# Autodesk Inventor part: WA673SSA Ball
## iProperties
Category: PARTsolutions
Created: 2011-07
Part Number: WA673SSA Ball
Catalog Web Link: www.cadenas.de
Description: Six types ball - Metric system sizes
Document SubType Name: Modeling
Designer: PARTsolutions
Density: 1 g/cm^3
NB: WA673SSA Ball
NN: Six types ball
NT: Metric system sizes
NBSYN: $ORDER. Ball
LINA: WA673SSA Ball
SD: 3.0
D: 6
B: 2.0
R: 0.08
ORDER: WA673SSA
CR: 242
COR: 94
CRF: 25
CORF: 9,5
LSG: 60 000
LSO: 71 000
MASS: 0.20
ORDER1: 673
D1: 7.2
D2: 7.2
C1: 0.6
C2: 0.6
WSS: WA673SSA
WDS: SSA
UTWF: FL673
FORSS: FLWA673SA
FORDS: SSA
DA1: 3,6
DA2: 4,1
DA: 5,4
RAS: 0,08
MASS1: 0.26
B1: 2.5
VERS: 3
X: 1.500
N: 9
O: 14.130
RB: 0.444
KT: DUMMY
SUPPLIER: NTN
ARTICLENO: WA673SSA Ball
BOMINFO: WA673SSA Ball
CREATOR: CADENAS GmbH
PSOL_IDENT_0: {\\10.0.0.251\ps_data\23d-libs\ntn\ball_roller_bearings\miniature_extra_small_bb\metric_system_sizes
PSOL_IDENT_1: \mss_ball.prj},179 {VTYP=3D},{NB=WA673SSA Ball},{LINA=WA673SSA Ball},{NN=Six types ball},{DATE=11.12
PSOL_IDENT_2: .2007 08:48:23},{GEOMDATE=02.04.2007 00:00:00},{VERSION=},{LINEID=12590},{LINESUBID=-1},{WBVAR=}  {N
PSOL_IDENT_3: B=WA673SSA Ball},{LINA=WA673SSA Ball},{KT=DUMMY},{IDNR=},{SD=3.0},{D=6},{B=2.0},{R=0.08},{ORDER=WA67
PSOL_IDENT_4: 3SSA},{CR=242},{COR=94},{CRF=25},{CORF=9,5},{LSG=60 000},{LSO=71 000},{MASS=0.20},{ORDER1=673},{D1=7
PSOL_IDENT_5: .2},{D2=7.2},{C1=0.6},{C2=0.6},{WSS=WA673SSA},{WDS=SSA},{UTWF=FL673},{FORSS=FLWA673SA},{FORDS=SSA},{
PSOL_IDENT_6: DA1=3,6},{DA2=4,1},{DA=5,4},{RAS=0,08},{MASS1=0.26},{B1=2.5},{VERS=3},{X=1.5},{N=9},{O=14.13},{RB=0.
PSOL_IDENT_7: 444}
Title: WA673SSA Ball
Author: Cadenas PARTsolutions
Comments: Metric system sizes
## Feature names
1. Revolution1
